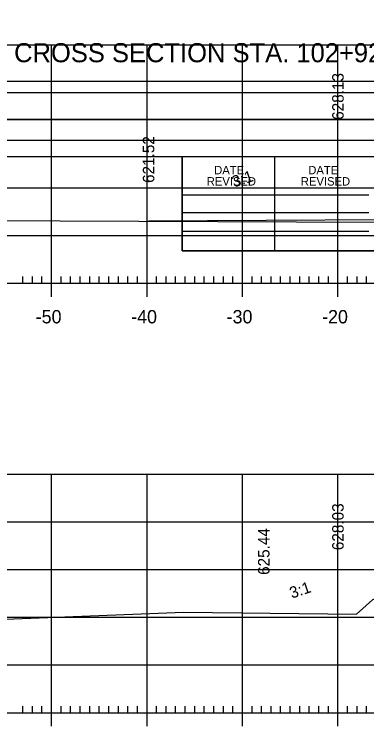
# Model space of a CAD drawing. Extents: x 1381471 to 1382703, y 370300 to 371487.
# Drawn here: x 1382082.7 to 1382119.6, y 370696.7 to 370772 of the extents above; entities that cross this region are included whole.
import ezdxf

# ---------------------------------------------------------------- set-up
doc = ezdxf.new("R2010")
doc.units = 0
for name, color, linetype in [('Level 15', 7, 'Continuous'), ('Level 26', 7, 'Continuous'), ('Level 45', 7, 'Continuous'), ('Level 6', 7, 'Continuous')]:
    doc.layers.add(name, color=color, linetype=linetype)

msp = doc.modelspace()

# ---------------------------------------------------------------- linework, layer by layer
at = {"layer": 'Level 26'}
for p, q in [((1381834.371, 370760.97), (1382167.705, 370760.97)), ((1381834.371, 370760.966), (1382167.705, 370760.966))]:
    msp.add_line(p, q, dxfattribs=at)
for points in [[(1381834.365, 370974.304), (1382167.705, 370974.304), (1382167.705, 370760.966), (1381834.365, 370760.966)], [(1382080.692, 370970.409), (1382100.312, 370970.409), (1382100.312, 370960.529), (1382116.424, 370960.529), (1382139.624, 370960.529), (1382139.624, 370927.859), (1382162.831, 370927.859), (1382162.952, 370764.949), (1381846.772, 370764.949), (1381846.772, 370970.409)], [(1381834.365, 370760.966), (1382167.705, 370760.966), (1382167.705, 370547.628), (1381834.365, 370547.628)], [(1382080.692, 370757.071), (1382100.312, 370757.071), (1382100.312, 370747.191), (1382116.424, 370747.191), (1382139.624, 370747.191), (1382139.624, 370714.521), (1382162.831, 370714.521), (1382162.952, 370551.611), (1381846.772, 370551.611), (1381846.772, 370757.071)]]:
    msp.add_lwpolyline(points, close=True, dxfattribs=at)
at = {"layer": 'Level 45'}
for p, q in [((1381996.613, 370768.782), (1382276.613, 370768.782)), ((1382086.613, 370743.782), (1382086.613, 370768.782)), ((1382096.613, 370743.782), (1382096.613, 370768.782)), ((1382106.613, 370743.782), (1382106.613, 370768.782)), ((1382116.613, 370743.782), (1382116.613, 370768.782)), ((1381996.613, 370763.782), (1382276.613, 370763.782)), ((1381996.613, 370758.782), (1382276.613, 370758.782)), ((1381996.613, 370753.782), (1382276.613, 370753.782)), ((1382174.997, 370750.783), (1382096.775, 370750.298)), ((1381996.613, 370748.782), (1382276.613, 370748.782)), ((1382086.613, 370742.382), (1382086.613, 370745.182)), ((1382096.613, 370742.382), (1382096.613, 370745.182)), ((1382106.613, 370742.382), (1382106.613, 370745.182)), ((1382116.613, 370742.382), (1382116.613, 370745.182)), ((1382083.613, 370743.782), (1382083.613, 370744.482)), ((1382084.613, 370743.782), (1382084.613, 370744.482)), ((1382085.613, 370743.782), (1382085.613, 370744.482)), ((1382087.613, 370743.782), (1382087.613, 370744.482)), ((1382088.613, 370743.782), (1382088.613, 370744.482)), ((1382089.613, 370743.782), (1382089.613, 370744.482)), ((1382090.613, 370743.782), (1382090.613, 370744.482)), ((1382091.613, 370743.782), (1382091.613, 370744.482)), ((1382092.613, 370743.782), (1382092.613, 370744.482)), ((1382093.613, 370743.782), (1382093.613, 370744.482)), ((1382094.613, 370743.782), (1382094.613, 370744.482)), ((1382095.613, 370743.782), (1382095.613, 370744.482)), ((1382097.613, 370743.782), (1382097.613, 370744.482)), ((1382098.613, 370743.782), (1382098.613, 370744.482)), ((1382099.613, 370743.782), (1382099.613, 370744.482)), ((1382100.613, 370743.782), (1382100.613, 370744.482)), ((1382101.613, 370743.782), (1382101.613, 370744.482)), ((1382102.613, 370743.782), (1382102.613, 370744.482)), ((1382103.613, 370743.782), (1382103.613, 370744.482)), ((1382104.613, 370743.782), (1382104.613, 370744.482)), ((1382105.613, 370743.782), (1382105.613, 370744.482)), ((1382107.613, 370743.782), (1382107.613, 370744.482)), ((1382108.613, 370743.782), (1382108.613, 370744.482)), ((1382109.613, 370743.782), (1382109.613, 370744.482)), ((1382110.613, 370743.782), (1382110.613, 370744.482)), ((1382111.613, 370743.782), (1382111.613, 370744.482)), ((1382112.613, 370743.782), (1382112.613, 370744.482)), ((1382113.613, 370743.782), (1382113.613, 370744.482)), ((1382114.613, 370743.782), (1382114.613, 370744.482)), ((1382115.613, 370743.782), (1382115.613, 370744.482)), ((1382117.613, 370743.782), (1382117.613, 370744.482)), ((1382118.613, 370743.782), (1382118.613, 370744.482)), ((1382119.613, 370743.782), (1382119.613, 370744.482)), ((1381996.613, 370743.782), (1382276.613, 370743.782)), ((1381996.613, 370743.782), (1382276.613, 370743.782)), ((1381996.613, 370723.782), (1382276.613, 370723.782)), ((1382086.613, 370698.782), (1382086.613, 370723.782)), ((1382096.613, 370698.782), (1382096.613, 370723.782)), ((1382106.613, 370698.782), (1382106.613, 370723.782)), ((1382116.613, 370698.782), (1382116.613, 370723.782)), ((1381996.613, 370718.782), (1382276.613, 370718.782)), ((1381996.613, 370713.782), (1382276.613, 370713.782)), ((1381996.613, 370708.782), (1382276.613, 370708.782)), ((1381996.613, 370703.782), (1382276.613, 370703.782)), ((1382086.613, 370697.382), (1382086.613, 370700.182)), ((1382096.613, 370697.382), (1382096.613, 370700.182)), ((1382106.613, 370697.382), (1382106.613, 370700.182)), ((1382116.613, 370697.382), (1382116.613, 370700.182)), ((1382083.613, 370698.782), (1382083.613, 370699.482)), ((1382084.613, 370698.782), (1382084.613, 370699.482)), ((1382085.613, 370698.782), (1382085.613, 370699.482)), ((1382087.613, 370698.782), (1382087.613, 370699.482)), ((1382088.613, 370698.782), (1382088.613, 370699.482)), ((1382089.613, 370698.782), (1382089.613, 370699.482)), ((1382090.613, 370698.782), (1382090.613, 370699.482)), ((1382091.613, 370698.782), (1382091.613, 370699.482)), ((1382092.613, 370698.782), (1382092.613, 370699.482)), ((1382093.613, 370698.782), (1382093.613, 370699.482)), ((1382094.613, 370698.782), (1382094.613, 370699.482)), ((1382095.613, 370698.782), (1382095.613, 370699.482)), ((1382097.613, 370698.782), (1382097.613, 370699.482)), ((1382098.613, 370698.782), (1382098.613, 370699.482)), ((1382099.613, 370698.782), (1382099.613, 370699.482)), ((1382100.613, 370698.782), (1382100.613, 370699.482)), ((1382101.613, 370698.782), (1382101.613, 370699.482)), ((1382102.613, 370698.782), (1382102.613, 370699.482)), ((1382103.613, 370698.782), (1382103.613, 370699.482)), ((1382104.613, 370698.782), (1382104.613, 370699.482)), ((1382105.613, 370698.782), (1382105.613, 370699.482)), ((1382107.613, 370698.782), (1382107.613, 370699.482)), ((1382108.613, 370698.782), (1382108.613, 370699.482)), ((1382109.613, 370698.782), (1382109.613, 370699.482)), ((1382110.613, 370698.782), (1382110.613, 370699.482)), ((1382111.613, 370698.782), (1382111.613, 370699.482)), ((1382112.613, 370698.782), (1382112.613, 370699.482)), ((1382113.613, 370698.782), (1382113.613, 370699.482)), ((1382114.613, 370698.782), (1382114.613, 370699.482)), ((1382115.613, 370698.782), (1382115.613, 370699.482)), ((1382117.613, 370698.782), (1382117.613, 370699.482)), ((1382118.613, 370698.782), (1382118.613, 370699.482)), ((1382119.613, 370698.782), (1382119.613, 370699.482)), ((1381996.613, 370698.782), (1382276.613, 370698.782)), ((1381996.613, 370698.782), (1382276.613, 370698.782))]:
    msp.add_line(p, q, dxfattribs=at)
for points in [[(1381996.613, 370753.017), (1382013.215, 370752.868), (1382043.962, 370751.304), (1382060.077, 370750.923), (1382079.195, 370750.367), (1382120.539, 370750.205), (1382124.194, 370751.072), (1382125.195, 370751.346), (1382144.863, 370749.405), (1382146.067, 370749.242), (1382146.549, 370749.133), (1382150, 370748.827), (1382154.139, 370749.707), (1382161.696, 370750.295), (1382170.643, 370750.819), (1382184.535, 370750.705)], [(1382060.367, 370707.751), (1382100.468, 370709.331), (1382118.576, 370709.098), (1382120.238, 370710.623), (1382120.286, 370710.659), (1382120.347, 370710.689), (1382123.039, 370711.114), (1382123.727, 370713.168), (1382124.72, 370713.303), (1382125.344, 370713.346), (1382132.324, 370713.557), (1382136.499, 370713.689), (1382144.315, 370713.601), (1382148.355, 370713.548), (1382158.234, 370712.298), (1382160.603, 370711.997), (1382161.689, 370711.648), (1382165.177, 370710.545), (1382165.231, 370710.632), (1382167.416, 370709.684), (1382168.189, 370708.364), (1382172.246, 370707.627), (1382183.305, 370707.806)]]:
    msp.add_lwpolyline(points, dxfattribs=at)
at = {"layer": 'Level 6'}
for p, q in [((1382162.952, 370764.949), (1381846.772, 370764.949)), ((1381846.772, 370757.071), (1382162.952, 370757.071)), ((1382100.312, 370747.191), (1382100.312, 370757.071)), ((1382109.992, 370747.191), (1382109.992, 370757.071)), ((1382100.312, 370753.051), (1382119.852, 370753.051)), ((1382100.312, 370751.191), (1382119.852, 370751.191)), ((1382100.312, 370749.251), (1382119.852, 370749.251)), ((1382162.952, 370747.191), (1382100.312, 370747.191))]:
    msp.add_line(p, q, dxfattribs=at)

# ---------------------------------------------------------------- texts
at = {"layer": 'Level 15'}
msp.add_text('CROSS SECTION STA. 102+92 TO STA. 104+18', height=2, dxfattribs=at).set_placement((1382082.689, 370766.949))
at = {"layer": 'Level 45'}
for s, rotation, p in [('628.13', 90, (1382117.213, 370760.911)), ('621.52', 90, (1382097.375, 370754.298)), ('3:1', 18.43493, (1382105.747, 370753.816)), ('628.03', 90, (1382117.213, 370715.812)), ('625.44', 90, (1382109.446, 370713.223)), ('3:1', 18.43493, (1382111.783, 370710.729))]:
    msp.add_text(s, height=1.2, rotation=rotation, dxfattribs=at).set_placement(p)
for s, p in [('-50', (1382084.954, 370739.582)), ('-40', (1382094.954, 370739.582)), ('-30', (1382104.954, 370739.582)), ('-20', (1382114.954, 370739.582))]:
    msp.add_text(s, height=1.4, dxfattribs=at).set_placement(p)
at = {"layer": 'Level 6'}
for s, p in [('DATE', (1382103.65, 370755.207)), ('DATE', (1382113.51, 370755.207)), ('REVISED', (1382102.87, 370754.027)), ('REVISED', (1382112.73, 370754.027))]:
    msp.add_text(s, height=0.8792, rotation=360, dxfattribs=at).set_placement(p)

doc.saveas('drawing.dxf')
